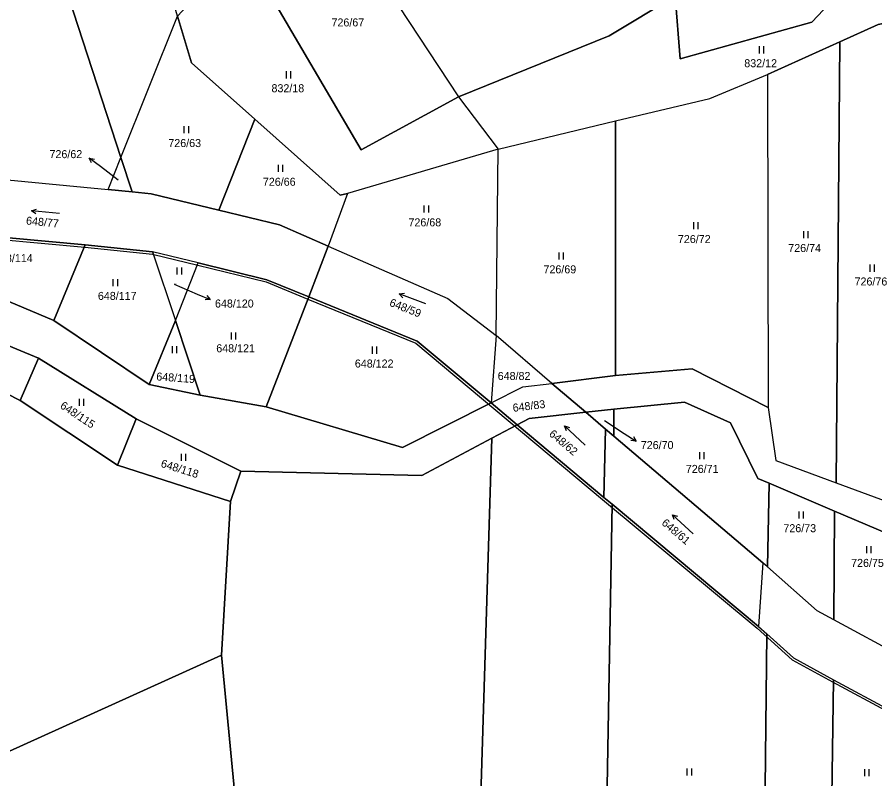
# Model space of a CAD drawing. Extents: x -654083 to -650132, y -1099819 to -1096699.
# Drawn here: x -652854.1 to -652672, y -1098652.1 to -1098490.3 of the extents above; entities that cross this region are included whole.
import ezdxf

# ---------------------------------------------------------------- set-up
doc = ezdxf.new("R2010")
doc.units = 0
for name, color, linetype in [('Obvody jako plochy', 7, 'Continuous'), ('Ostatní hranice', 7, 'Continuous'), ('Parcelní čísla', 7, 'Continuous'), ('Prvky pro prodl_ par_ č_', 7, 'Continuous'), ('Značky kultur', 7, 'Continuous')]:
    doc.layers.add(name, color=color, linetype=linetype)

msp = doc.modelspace()

# ---------------------------------------------------------------- linework, layer by layer
at = {"layer": 'Obvody jako plochy'}
for points in [[(-652728.41, -1098494.29), (-652714.37, -1098485.84), (-652713.29, -1098499.17), (-652685.38, -1098491.4), (-652671.82, -1098477.02), (-652667.54, -1098475.57), (-652641.04, -1098388.64), (-652638.12, -1098389.25), (-652614.62, -1098394.13), (-652588.09, -1098398.68), (-652559.94, -1098399.93), (-652559.53, -1098399.2), (-652587.6, -1098395.75), (-652614.36, -1098392.06), (-652643.16, -1098386.92), (-652651.86, -1098415.85), (-652676.91, -1098408.12), (-652688.78, -1098404.45), (-652709.75, -1098397.98), (-652723.48, -1098441.82), (-652727.3, -1098440.63), (-652759.46, -1098430.59), (-652789.97, -1098462.34), (-652760.41, -1098507.23)], [(-652834.21, -1098452.89), (-652834.38, -1098439.26), (-652834.71, -1098434.17), (-652837.7, -1098418.25), (-652838.36, -1098414.99), (-652843.92, -1098406.01), (-652860.99, -1098442.13), (-652852.29, -1098458.12), (-652832.08, -1098520.17), (-652820.05, -1098490.16), (-652824.83, -1098474.15), (-652827.35, -1098466.95), (-652830.86, -1098459.21)], [(-652832.08, -1098520.17), (-652852.29, -1098458.12), (-652860.99, -1098442.13), (-652898.03, -1098520.27), (-652894.58, -1098521.17), (-652834.8, -1098526.96)], [(-652791.68, -1098459.68), (-652789.97, -1098462.34), (-652760.41, -1098507.23), (-652781.04, -1098518.5), (-652801.74, -1098483.24), (-652802.3, -1098471.09)], [(-652802.3, -1098471.09), (-652801.74, -1098483.24), (-652781.04, -1098518.5), (-652760.41, -1098507.23), (-652751.94, -1098518.37), (-652783.97, -1098527.81), (-652785.55, -1098528.16), (-652803.63, -1098512.03), (-652817.07, -1098500.04), (-652820.05, -1098490.16)], [(-652694.73, -1098502.53), (-652679.4, -1098495.58), (-652671.23, -1098491.91), (-652664.98, -1098490.67), (-652634.74, -1098485.26), (-652614.2, -1098480.89), (-652608.7, -1098479.62), (-652605.25, -1098472.56), (-652626.03, -1098473.62), (-652646.8, -1098474.59), (-652667.54, -1098475.57), (-652671.82, -1098477.02), (-652685.38, -1098491.4), (-652713.29, -1098499.17), (-652714.37, -1098485.84), (-652728.41, -1098494.29), (-652760.41, -1098507.23), (-652751.94, -1098518.37), (-652727.05, -1098512.36), (-652707.01, -1098507.59)], [(-652817.07, -1098500.04), (-652803.63, -1098512.03), (-652811.29, -1098531.32), (-652825.66, -1098527.85), (-652829.72, -1098527.45), (-652832.08, -1098520.17), (-652820.05, -1098490.16)], [(-652680.19, -1098589.19), (-652669.4, -1098593.19), (-652665.72, -1098592.51), (-652664.98, -1098490.67), (-652671.23, -1098491.91), (-652679.4, -1098495.58)], [(-652692.97, -1098584.45), (-652680.19, -1098589.19), (-652679.4, -1098495.58), (-652694.73, -1098502.53), (-652694.63, -1098573.23)], [(-652694.73, -1098502.53), (-652694.63, -1098573.23), (-652710.79, -1098564.97), (-652727.07, -1098566.44), (-652727.05, -1098512.36), (-652707.01, -1098507.59)], [(-652825.66, -1098527.85), (-652811.29, -1098531.32), (-652798.4, -1098534.44), (-652788.05, -1098538.95), (-652792.17, -1098549.72), (-652801.07, -1098546.08), (-652815.7, -1098542.53), (-652825.36, -1098540.18), (-652839.65, -1098538.68), (-652896.86, -1098533.41), (-652903.15, -1098530.75), (-652909.39, -1098528.07), (-652930.13, -1098516.24), (-652933.41, -1098508.45), (-652930.82, -1098510.75), (-652929.22, -1098512.17), (-652898.03, -1098520.27), (-652894.58, -1098521.17), (-652834.8, -1098526.96), (-652829.72, -1098527.45)], [(-652803.63, -1098512.03), (-652785.55, -1098528.16), (-652783.97, -1098527.81), (-652788.05, -1098538.95), (-652798.4, -1098534.44), (-652811.29, -1098531.32)], [(-652727.05, -1098512.36), (-652727.07, -1098566.44), (-652740.54, -1098568.09), (-652752.4, -1098557.96), (-652751.94, -1098518.37)], [(-652753.45, -1098572.24), (-652747.93, -1098576.88), (-652753.29, -1098579.73), (-652768.15, -1098587.64), (-652806.64, -1098586.72), (-652828.86, -1098575.61), (-652849.59, -1098562.77), (-652907.06, -1098538.92), (-652935.5, -1098521.71), (-652938.33, -1098520), (-652939.53, -1098517.11), (-652933.7, -1098522.03), (-652896.86, -1098533.41), (-652846.32, -1098554.74), (-652826.06, -1098568.34), (-652815.24, -1098570.62), (-652801.21, -1098573.05), (-652772.27, -1098581.71)], [(-652752.4, -1098557.96), (-652751.94, -1098518.37), (-652783.97, -1098527.81), (-652788.05, -1098538.95), (-652762.62, -1098550.04)], [(-652832.08, -1098520.17), (-652829.72, -1098527.45), (-652834.8, -1098526.96)], [(-652839.65, -1098538.68), (-652846.32, -1098554.74), (-652896.86, -1098533.41)], [(-652849.59, -1098562.77), (-652853.46, -1098571.74), (-652862.42, -1098567.2), (-652881.5, -1098566.38), (-652913.05, -1098552.12), (-652907.06, -1098538.92)], [(-652825.36, -1098540.18), (-652820.49, -1098554.72), (-652826.06, -1098568.34), (-652846.32, -1098554.74), (-652839.65, -1098538.68)], [(-652820.49, -1098554.72), (-652815.7, -1098542.53), (-652825.36, -1098540.18)], [(-652762.62, -1098550.04), (-652752.4, -1098557.96), (-652753.45, -1098572.24), (-652769.19, -1098559.12), (-652792.17, -1098549.72), (-652788.05, -1098538.95)], [(-652792.17, -1098549.72), (-652801.21, -1098573.05), (-652815.24, -1098570.62), (-652820.49, -1098554.72), (-652815.7, -1098542.53), (-652801.07, -1098546.08)], [(-652792.17, -1098549.72), (-652769.19, -1098559.12), (-652753.45, -1098572.24), (-652772.27, -1098581.71), (-652801.21, -1098573.05)], [(-652810.73, -1098625.77), (-652867.83, -1098651.63), (-652906.43, -1098611.58), (-652931.99, -1098569.39), (-652913.05, -1098552.12), (-652881.5, -1098566.38), (-652862.42, -1098567.2), (-652853.46, -1098571.74), (-652832.83, -1098585.45), (-652808.83, -1098593.15)], [(-652820.49, -1098554.72), (-652815.24, -1098570.62), (-652826.06, -1098568.34)], [(-652753.45, -1098572.24), (-652746.7, -1098568.84), (-652740.54, -1098568.09), (-652752.4, -1098557.96)], [(-652828.86, -1098575.61), (-652832.83, -1098585.45), (-652853.46, -1098571.74), (-652849.59, -1098562.77)], [(-652740.54, -1098568.09), (-652733.36, -1098574.2), (-652745.41, -1098575.54), (-652747.93, -1098576.88), (-652753.45, -1098572.24), (-652746.7, -1098568.84)], [(-652727.4, -1098573.54), (-652712.38, -1098572.09), (-652702.64, -1098576.45), (-652696.83, -1098588.26), (-652694.38, -1098589.3), (-652694.75, -1098607.06), (-652695.77, -1098606.16), (-652727.43, -1098579.28)], [(-652733.36, -1098574.2), (-652729.15, -1098577.79), (-652729.55, -1098592.33), (-652747.93, -1098576.88), (-652745.41, -1098575.54)], [(-652733.36, -1098574.2), (-652727.4, -1098573.54), (-652727.43, -1098579.28), (-652729.15, -1098577.79)], [(-652806.64, -1098586.72), (-652808.83, -1098593.15), (-652832.83, -1098585.45), (-652828.86, -1098575.61)], [(-652729.55, -1098592.33), (-652727.76, -1098593.76), (-652730.78, -1098765.53), (-652740.97, -1098767.26), (-652739.31, -1098758.15), (-652738.8, -1098756.89), (-652758.55, -1098749.79), (-652753.29, -1098579.73), (-652747.93, -1098576.88)], [(-652727.43, -1098579.28), (-652695.77, -1098606.16), (-652696.66, -1098619.71), (-652727.76, -1098593.76), (-652729.55, -1098592.33), (-652729.15, -1098577.79)], [(-652758.55, -1098749.79), (-652800.2, -1098738.06), (-652800.46, -1098733.14), (-652810.73, -1098625.77), (-652808.83, -1098593.15), (-652806.64, -1098586.72), (-652768.15, -1098587.64), (-652753.29, -1098579.73)], [(-652680.52, -1098595.22), (-652680.64, -1098618.31), (-652684.24, -1098616.37), (-652694.75, -1098607.06), (-652694.38, -1098589.3)], [(-652696.66, -1098619.71), (-652694.91, -1098621.29), (-652696.52, -1098771.41), (-652696.54, -1098773.4), (-652709.73, -1098769.07), (-652718.34, -1098766.78), (-652730.78, -1098765.53), (-652727.76, -1098593.76)], [(-652665.86, -1098600.2), (-652666, -1098626.21), (-652680.64, -1098618.31), (-652680.52, -1098595.22), (-652669.38, -1098599.98)], [(-652689.27, -1098626.38), (-652680.73, -1098631), (-652682.41, -1098750.08), (-652696.52, -1098771.41), (-652694.91, -1098621.29)], [(-652810.73, -1098625.77), (-652800.46, -1098733.14), (-652878.05, -1098733.75), (-652868.26, -1098655.1), (-652867.83, -1098651.63)], [(-652680.73, -1098631), (-652668.64, -1098637.55), (-652666.15, -1098638.15), (-652667.3, -1098727.98), (-652682.41, -1098750.08)]]:
    msp.add_lwpolyline(points, close=True, dxfattribs=at)
for points in [[(-652669.38, -1098599.98), (-652680.52, -1098595.22), (-652694.38, -1098589.3), (-652696.83, -1098588.26), (-652702.64, -1098576.45), (-652712.38, -1098572.09), (-652727.4, -1098573.54), (-652733.36, -1098574.2), (-652740.54, -1098568.09), (-652727.07, -1098566.44), (-652710.79, -1098564.97), (-652694.63, -1098573.23), (-652692.97, -1098584.45), (-652680.19, -1098589.19), (-652669.4, -1098593.19)], [(-652666, -1098626.21), (-652680.64, -1098618.31), (-652684.24, -1098616.37), (-652694.75, -1098607.06), (-652695.77, -1098606.16), (-652696.66, -1098619.71), (-652694.91, -1098621.29), (-652689.27, -1098626.38), (-652680.73, -1098631), (-652668.64, -1098637.55)]]:
    msp.add_lwpolyline(points, dxfattribs=at)
at = {"layer": 'Ostatní hranice'}
for p, q in [((-652897.05, -1098533.87), (-652839.74, -1098539.17)), ((-652839.74, -1098539.17), (-652825.39, -1098540.68)), ((-652825.39, -1098540.68), (-652815.76, -1098543.03)), ((-652815.76, -1098543.03), (-652801.25, -1098546.55)), ((-652801.25, -1098546.55), (-652792.35, -1098550.19)), ((-652792.35, -1098550.19), (-652769.48, -1098559.53)), ((-652769.48, -1098559.53), (-652729.83, -1098592.74)), ((-652729.83, -1098592.74), (-652696.97, -1098620.1)), ((-652696.97, -1098620.1), (-652689.55, -1098626.79)), ((-652689.55, -1098626.79), (-652680.98, -1098631.44)), ((-652680.98, -1098631.44), (-652668.87, -1098638))]:
    msp.add_line(p, q, dxfattribs=at)
at = {"layer": 'Prvky pro prodl_ par_ č_'}
for p, q in [((-652836.4, -1098522.08), (-652838.79, -1098520.27)), ((-652832.64, -1098524.93), (-652836.4, -1098522.08)), ((-652820.8, -1098547.05), (-652815.87, -1098549.13)), ((-652815.87, -1098549.13), (-652813.1, -1098550.29)), ((-652729.4, -1098575.94), (-652725.18, -1098578.7)), ((-652725.18, -1098578.7), (-652722.67, -1098580.34))]:
    msp.add_line(p, q, dxfattribs=at)
for points in [[(-652838.3, -1098521.27), (-652838.79, -1098520.27), (-652837.69, -1098520.47)], [(-652813.83, -1098549.44), (-652813.1, -1098550.29), (-652814.22, -1098550.37)], [(-652723.23, -1098579.38), (-652722.67, -1098580.34), (-652723.78, -1098580.21)]]:
    msp.add_lwpolyline(points, dxfattribs=at)
at = {"layer": 'Značky kultur'}
for p, q in [((-652696.55, -1098496.53), (-652696.55, -1098498.03)), ((-652695.53, -1098498.03), (-652695.53, -1098496.53)), ((-652797, -1098501.84), (-652797, -1098503.34)), ((-652795.97, -1098503.34), (-652795.97, -1098501.84)), ((-652818.69, -1098513.49), (-652818.69, -1098514.99)), ((-652817.67, -1098514.99), (-652817.67, -1098513.49)), ((-652798.69, -1098521.71), (-652798.69, -1098523.21)), ((-652797.67, -1098523.21), (-652797.67, -1098521.71)), ((-652767.74, -1098530.32), (-652767.74, -1098531.82)), ((-652766.71, -1098531.82), (-652766.71, -1098530.32)), ((-652845.09, -1098532.02), (-652851.07, -1098531.48)), ((-652710.51, -1098533.86), (-652710.51, -1098535.36)), ((-652709.48, -1098535.36), (-652709.48, -1098533.86)), ((-652687.14, -1098535.77), (-652687.14, -1098537.27)), ((-652686.11, -1098537.27), (-652686.11, -1098535.77)), ((-652739.09, -1098540.29), (-652739.09, -1098541.79)), ((-652738.07, -1098541.79), (-652738.07, -1098540.29)), ((-652820.19, -1098543.5), (-652820.19, -1098545)), ((-652819.17, -1098545), (-652819.17, -1098543.5)), ((-652673.06, -1098542.88), (-652673.06, -1098544.38)), ((-652672.04, -1098544.38), (-652672.04, -1098542.88)), ((-652833.77, -1098545.94), (-652833.77, -1098547.44)), ((-652832.74, -1098547.44), (-652832.74, -1098545.94)), ((-652767.34, -1098551.18), (-652772.96, -1098549.08)), ((-652808.67, -1098557.31), (-652808.67, -1098558.81)), ((-652807.65, -1098558.81), (-652807.65, -1098557.31)), ((-652821.19, -1098560.21), (-652821.19, -1098561.71)), ((-652820.17, -1098561.71), (-652820.17, -1098560.21)), ((-652778.73, -1098560.29), (-652778.73, -1098561.79)), ((-652777.7, -1098561.79), (-652777.7, -1098560.29)), ((-652840.96, -1098571.35), (-652840.96, -1098572.85)), ((-652839.94, -1098572.85), (-652839.94, -1098571.35)), ((-652733.45, -1098581.19), (-652737.87, -1098577.13)), ((-652819.31, -1098583.02), (-652819.31, -1098584.52)), ((-652818.29, -1098584.52), (-652818.29, -1098583.02)), ((-652709.2, -1098582.67), (-652709.2, -1098584.17)), ((-652708.18, -1098584.17), (-652708.18, -1098582.67)), ((-652710.56, -1098600.06), (-652714.96, -1098595.98)), ((-652688.1, -1098595.26), (-652688.1, -1098596.76)), ((-652687.08, -1098596.76), (-652687.08, -1098595.26)), ((-652673.75, -1098602.62), (-652673.75, -1098604.12)), ((-652672.72, -1098604.12), (-652672.72, -1098602.62)), ((-652711.86, -1098649.83), (-652711.86, -1098651.33)), ((-652710.83, -1098651.33), (-652710.83, -1098649.83)), ((-652674.18, -1098649.99), (-652674.18, -1098651.49)), ((-652673.16, -1098651.49), (-652673.16, -1098649.99))]:
    msp.add_line(p, q, dxfattribs=at)
for points in [[(-652850.12, -1098532.07), (-652851.07, -1098531.48), (-652850.03, -1098531.08)], [(-652772.2, -1098549.9), (-652772.96, -1098549.08), (-652771.85, -1098548.96)], [(-652737.47, -1098578.17), (-652737.87, -1098577.13), (-652736.79, -1098577.44)], [(-652714.56, -1098597.02), (-652714.96, -1098595.98), (-652713.88, -1098596.29)]]:
    msp.add_lwpolyline(points, dxfattribs=at)

# ---------------------------------------------------------------- texts
at = {"layer": 'Parcelní čísla'}
for s, height, p in [('726/67', 1.7, (-652787.36, -1098492.31)), ('832/12', 1.7, (-652699.69, -1098500.97)), ('832/18', 1.7, (-652800.1, -1098506.28)), ('726/63', 1.7, (-652822.01, -1098517.92)), ('726/66', 1.7, (-652801.93, -1098526.14)), ('726/68', 1.7, (-652771.01, -1098534.76)), ('726/72', 1.7, (-652713.79, -1098538.3)), ('726/74', 1.7, (-652690.35, -1098540.2)), ('648/114', 1.7, (-652859.03, -1098542.35)), ('726/69', 1.7, (-652742.34, -1098544.73)), ('726/76', 1.7, (-652676.27, -1098547.31)), ('648/120', 0.1, (-652820.8, -1098547.05)), ('648/117', 1.7, (-652836.97, -1098550.37)), ('648/121', 1.7, (-652811.83, -1098561.49)), ('648/122', 1.7, (-652782.4, -1098564.73)), ('648/82', 1.7, (-652752.06, -1098567.37)), ('726/71', 1.7, (-652712.11, -1098587.1)), ('726/73', 1.7, (-652691.39, -1098599.69)), ('726/75', 1.7, (-652677, -1098607.06))]:
    msp.add_text(s, height=height, dxfattribs=at).set_placement(p)
for s, height, rotation, p in [('726/62', 0.1, 72.063, (-652832.64, -1098524.93)), ('648/77', 1.7, 354.528, (-652852.28, -1098534.35)), ('648/59', 1.7, 338.391, (-652775.2, -1098551.58)), ('648/119', 1.7, 355.869, (-652824.61, -1098567.45)), ('648/115', 1.7, 326.34, (-652845.15, -1098573.2)), ('648/83', 1.7, 7.128, (-652748.77, -1098574.15)), ('726/70', 0.1, 320.526, (-652729.4, -1098575.94)), ('648/62', 1.7, 319.932, (-652741.3, -1098579.06)), ('648/118', 1.7, 342.648, (-652823.74, -1098585.79)), ('648/61', 1.7, 319.662, (-652717.39, -1098597.96))]:
    msp.add_text(s, height=height, rotation=rotation, dxfattribs=at).set_placement(p)
at = {"layer": 'Prvky pro prodl_ par_ č_'}
for s, p in [('726/62', (-652847.25, -1098520.27)), ('648/120', (-652812.1, -1098551.99)), ('726/70', (-652721.67, -1098582.04))]:
    msp.add_text(s, height=1.7, dxfattribs=at).set_placement(p)

doc.saveas('drawing.dxf')
